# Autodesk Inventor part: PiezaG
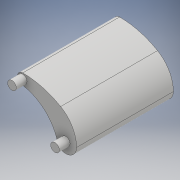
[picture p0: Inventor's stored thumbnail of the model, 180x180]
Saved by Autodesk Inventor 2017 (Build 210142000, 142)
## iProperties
Part Number: PiezaG
Material: Genérico
Document SubType Name: Modeling
Designer: Jaime
Density: 1 g/cm^3
Appearance: Valor por defecto
Author: Jaime
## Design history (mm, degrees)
sketch "Boceto1"
  geometry: L1 (0, 0)-(-10, 0); L2 (0, 0)-(0, -10); L3 (19.51, 0)-(4.755, 25.556); L4 (19.51, 0)-(-10, 0); L5 (40, -35.49)-(40, 35); L6 (40, -35.49)-(4.755, 25.556); L7 (0, 0)-(7.071, -7.071); L8 (0, 0)-(0, -10); A1 r 10 centre (0, 0) between (-10, 0) and (0, -10); A2 r 29.51 centre (19.51, 0) between (4.755, 25.556) and (-10, 0); A3 r 70.49 centre (40, -35.49) between (40, 35) and (4.755, 25.556); A4 r 5 centre (40, 30) between (40, 25) and (40, 35); A5 r 10 centre (0, 0) between (0, -10) and (5.09, -8.608); A6 r 40 centre (46.377, -14.488) between (40, 25) and (7.415, -5.435); A7 r 5 centre (2.545, -4.304) between (5.09, -8.608) and (7.415, -5.435); 1 further point
  constraints: 16 end point, 16 point on circle, 7 centre point, 5 tangent, 2 coincident, 2 point on line, 1 collinear, 1 horizontal alignment, 1 vertical alignment
  dimensions: "d3" = 10 radius of A1; "d8" = 45 vertical distance of L5.end L2.end; "d9" = 50 horizontal distance of L1.end L5.end; "d10" = 90 deg angle of L4 L5; "d11" = 60 deg angle of L4 L3; "d12" = 10 diameter of A4; "d13" = 45 deg angle of L8 L7; "d14" = 5 radius of A7; "d15" = 40 radius of A6; "d22" = 40 horizontal distance of point (0, 0) A4.centre (derived); "d23" = 30 vertical distance of point (0, 0) A4.centre (derived)
extrude "Extrusión1" new body sketch "Boceto1" distance "d16" = 90; taper "d17" = 0 deg
sketch "Boceto2"
  geometry: C1 r 4 at (0, 0); C2 r 4 at (-40, 30); A1 r 5 centre (-40, 30) between (-40, 35) and (-40, 25) reference; 1 further point
  constraints: 2 centre point, 2 coincident
  dimensions: "d18" = 8 diameter of C1; "d19" = 8 diameter of C2
extrude "Extrusión2" join sketch "Boceto2" distance "d20" = 10; taper "d21" = 0 deg
node "Sólido1"
